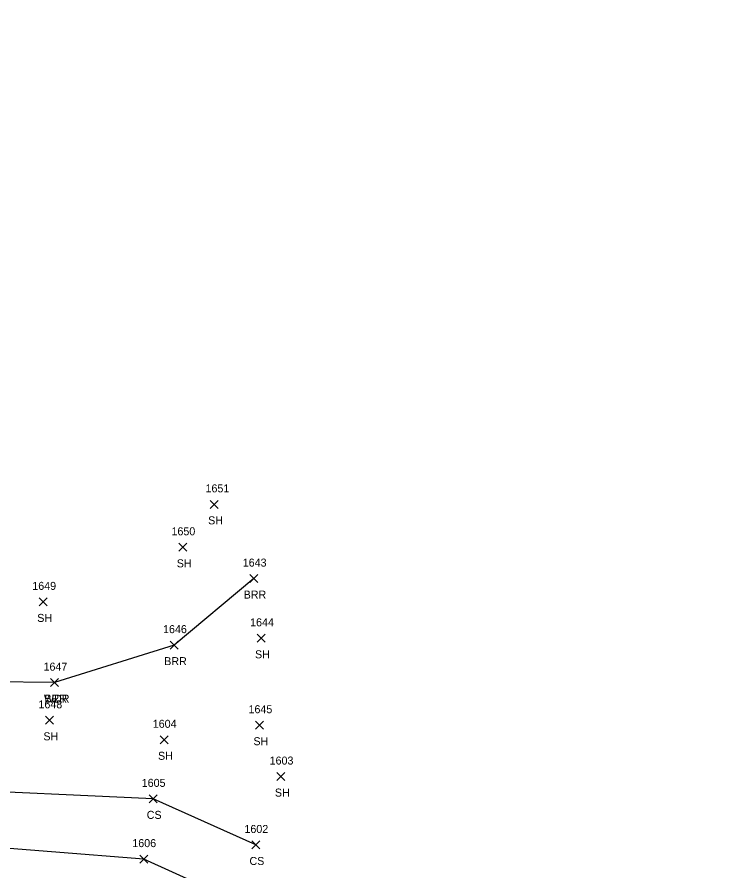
# Model space of a CAD drawing. Extents: x 1469310 to 1475157, y 493997 to 498873.
# Drawn here: x 1469630.2 to 1469805, y 498651.4 to 498864.7 of the extents above; entities that cross this region are included whole.
import ezdxf

# ---------------------------------------------------------------- set-up
doc = ezdxf.new("R2010")
doc.units = 0
for name, color, linetype in [('L_A', 7, 'Continuous'), ('L_I', 7, 'Continuous'), ('L_TIC', 7, 'Continuous'), ('LABL', 7, 'Continuous'), ('LAWA', 7, 'Continuous'), ('LELB', 7, 'Continuous')]:
    doc.layers.add(name, color=color, linetype=linetype)

msp = doc.modelspace()

# ---------------------------------------------------------------- linework, layer by layer
at = {"layer": 'L_TIC'}
for points in [[(1469678.5, 498741.98), (1469680.5, 498743.98)], [(1469680.5, 498741.98), (1469678.5, 498743.98)], [(1469670.65, 498731.25), (1469672.65, 498733.25)], [(1469672.65, 498731.25), (1469670.65, 498733.25)], [(1469688.38, 498723.43), (1469690.38, 498725.43)], [(1469690.38, 498723.43), (1469688.38, 498725.43)], [(1469635.77, 498717.61), (1469637.77, 498719.61)], [(1469637.77, 498717.61), (1469635.77, 498719.61)], [(1469690.22, 498708.51), (1469692.22, 498710.51)], [(1469692.22, 498708.51), (1469690.22, 498710.51)], [(1469668.51, 498706.8), (1469670.51, 498708.8)], [(1469670.51, 498706.8), (1469668.51, 498708.8)], [(1469638.57, 498697.43), (1469640.57, 498699.43)], [(1469640.57, 498697.43), (1469638.57, 498699.43)], [(1469638.57, 498697.43), (1469640.57, 498699.43)], [(1469640.57, 498697.43), (1469638.57, 498699.43)], [(1469637.3, 498688.02), (1469639.3, 498690.02)], [(1469639.3, 498688.02), (1469637.3, 498690.02)], [(1469689.82, 498686.79), (1469691.82, 498688.79)], [(1469691.82, 498686.79), (1469689.82, 498688.79)], [(1469665.96, 498683.15), (1469667.96, 498685.15)], [(1469667.96, 498683.15), (1469665.96, 498685.15)], [(1469695.18, 498673.96), (1469697.18, 498675.96)], [(1469697.18, 498673.96), (1469695.18, 498675.96)], [(1469663.2, 498668.39), (1469665.2, 498670.39)], [(1469665.2, 498668.39), (1469663.2, 498670.39)], [(1469688.87, 498656.87), (1469690.87, 498658.87)], [(1469690.87, 498656.87), (1469688.87, 498658.87)], [(1469660.91, 498653.33), (1469662.91, 498655.33)], [(1469662.91, 498653.33), (1469660.91, 498655.33)]]:
    msp.add_lwpolyline(points, dxfattribs=at)
at = {"layer": 'LABL'}
for points in [[(1469689.38, 498724.43), (1469669.51, 498707.8), (1469639.57, 498698.43)], [(1469804.95, 498565.12), (1469764.81, 498561.66), (1469749.08, 498576.22), (1469733.12, 498600.55), (1469716.5, 498617.67), (1469685.26, 498643.73), (1469661.91, 498654.33), (1469615.65, 498658), (1469588.27, 498643.44), (1469563.61, 498633.27)]]:
    msp.add_lwpolyline(points, dxfattribs=at)
at = {"layer": 'LAWA'}
msp.add_lwpolyline([(1469639.57, 498698.43), (1469608.35, 498698.81), (1469602.51, 498699.12), (1469553.35, 498720.92), (1469557.66, 498736.35), (1469502.31, 498785.09), (1469489.42, 498793.62), (1469479.51, 498786.07), (1469473.54, 498782.36), (1469463.54, 498781.5), (1469427.61, 498811.79), (1469409.37, 498828.74), (1469393.62, 498848.43), (1469395.42, 498864.75)], dxfattribs=at)
at = {"layer": 'LELB'}
msp.add_lwpolyline([(1469689.87, 498657.87), (1469664.2, 498669.39), (1469609.73, 498671.93), (1469582.14, 498658.76), (1469563.4, 498646.02), (1469554.48, 498659.45), (1469546.06, 498676.67), (1469525.38, 498698.23), (1469503.85, 498725.44), (1469472.45, 498754.54), (1469455.13, 498777.29), (1469419.87, 498802.33), (1469400.99, 498819.04), (1469383.05, 498844.76)], dxfattribs=at)

# ---------------------------------------------------------------- texts
at = {"layer": 'L_A'}
for s, p in [('SH', (1469677.99, 498737.98)), ('SH', (1469670.14, 498727.25)), ('BRR', (1469686.87, 498719.43)), ('SH', (1469635.25, 498713.61)), ('SH', (1469689.71, 498704.51)), ('BRR', (1469667, 498702.8)), ('WDR', (1469636.93, 498693.43)), ('BRR', (1469637.05, 498693.43)), ('SH', (1469636.79, 498684.02)), ('SH', (1469689.31, 498682.79)), ('SH', (1469665.45, 498679.15)), ('SH', (1469694.67, 498669.96)), ('CS', (1469662.64, 498664.39)), ('CS', (1469688.32, 498652.87))]:
    msp.add_text(s, height=2, dxfattribs=at).set_placement(p)
at = {"layer": 'L_I'}
for s, p in [('1651', (1469677.33, 498745.98)), ('1650', (1469668.82, 498735.25)), ('1643', (1469686.64, 498727.43)), ('1649', (1469634.02, 498721.61)), ('1644', (1469688.48, 498712.51)), ('1646', (1469666.71, 498710.8)), ('1647', (1469636.83, 498701.43)), ('1647', (1469636.83, 498701.43)), ('1648', (1469635.56, 498692.02)), ('1645', (1469688.08, 498690.79)), ('1604', (1469664.14, 498687.15)), ('1603', (1469693.36, 498677.96)), ('1605', (1469661.38, 498672.39)), ('1602', (1469687.06, 498660.87)), ('1606', (1469659.03, 498657.33))]:
    msp.add_text(s, height=2, dxfattribs=at).set_placement(p)

doc.saveas('drawing.dxf')
